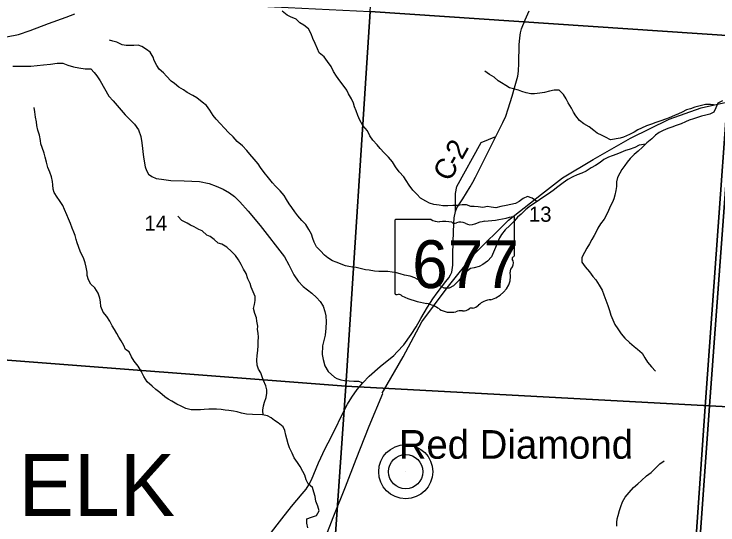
# Model space of a CAD drawing. Extents: x 0 to 34, y 0 to 22.
# Drawn here: x 3.275 to 5.215, y 15.589 to 16.998 of the extents above; entities that cross this region are included whole.
import ezdxf

# ---------------------------------------------------------------- set-up
doc = ezdxf.new("R2010")
doc.units = 0
for name, color, linetype in [('GM_X_County_Road', 7, 'Continuous'), ('GM_X_County_Road_Text', 7, 'Continuous'), ('GM_X_Minor_River', 7, 'Continuous'), ('GM_X_Rail_Line', 7, 'Continuous'), ('GM_X_Section', 7, 'Continuous'), ('GM_X_Section_Text', 7, 'Continuous'), ('GM_X_State_Location', 7, 'Continuous'), ('GM_X_State_Route', 7, 'Continuous'), ('GM_X_State_Shield', 7, 'Continuous'), ('GM_X_Township_Road', 7, 'Continuous'), ('GM_X_Township_Text', 7, 'Continuous'), ('GM_X_Unincorporated', 7, 'Continuous'), ('GM_X_Unincorporated_Location', 7, 'Continuous'), ('GM_X_Unincorporated_Text', 7, 'Continuous'), ('SC_Scratch1', 7, 'Continuous')]:
    doc.layers.add(name, color=color, linetype=linetype)

msp = doc.modelspace()

# ---------------------------------------------------------------- linework, layer by layer
at = {"layer": 'GM_X_County_Road'}
msp.add_lwpolyline([(4.4912, 16.4535), (4.4918, 16.5034), (4.4951, 16.5222), (4.5626, 16.6436), (4.6031, 16.6603)], dxfattribs=at)
at = {"layer": 'GM_X_Minor_River'}
for points in [[(4.7156, 16.481), (4.7031, 16.4897), (4.6902, 16.4946), (4.6781, 16.4889), (4.6668, 16.4809), (4.6565, 16.4759), (4.6441, 16.4725), (4.6312, 16.4698), (4.6165, 16.4671), (4.6028, 16.4633), (4.5896, 16.4655), (4.5794, 16.467), (4.5669, 16.4643), (4.5536, 16.4658), (4.5434, 16.4669), (4.5336, 16.4669), (4.5214, 16.4714), (4.5097, 16.4714), (4.498, 16.4702), (4.484, 16.4698), (4.4707, 16.4694), (4.4563, 16.469), (4.4461, 16.4705), (4.4321, 16.4731), (4.4203, 16.4765), (4.4093, 16.4822), (4.3953, 16.4897), (4.3851, 16.5014), (4.374, 16.5124), (4.3638, 16.526), (4.3554, 16.5393), (4.3493, 16.5491), (4.336, 16.5627), (4.3265, 16.5768), (4.3178, 16.5904), (4.3071, 16.6033), (4.2953, 16.6154), (4.2839, 16.6275), (4.2752, 16.6373), (4.2638, 16.6498), (4.2551, 16.6619), (4.2486, 16.6755), (4.2364, 16.6903), (4.228, 16.7054), (4.2223, 16.7179), (4.2177, 16.7308), (4.2135, 16.7418), (4.2101, 16.752), (4.2051, 16.7645), (4.1964, 16.7782), (4.1918, 16.7884), (4.1819, 16.802), (4.1728, 16.8134), (4.1633, 16.8262), (4.1553, 16.8395), (4.1488, 16.8535), (4.1389, 16.8668), (4.1294, 16.8796), (4.1162, 16.8906), (4.1112, 16.9016), (4.1047, 16.9171), (4.0982, 16.9304), (4.0933, 16.9432), (4.086, 16.9569), (4.0731, 16.9671), (4.0625, 16.9739), (4.0523, 16.9837), (4.0371, 16.9901), (4.0276, 16.995), (4.0136, 17.0056)], [(3.9046, 16.6345), (3.8902, 16.6462), (3.8784, 16.6595), (3.8663, 16.6712), (3.8545, 16.6833), (3.8431, 16.6965), (3.8317, 16.7083), (3.8237, 16.7181), (3.8146, 16.7332), (3.8051, 16.7457), (3.7937, 16.7552), (3.7789, 16.7669), (3.7679, 16.7737), (3.7523, 16.7816), (3.7421, 16.7888), (3.7292, 16.7964), (3.7174, 16.8066), (3.7076, 16.813), (3.6947, 16.8262), (3.6871, 16.8361), (3.6745, 16.8459), (3.6681, 16.8557), (3.6612, 16.8694), (3.6578, 16.8788), (3.6498, 16.8932), (3.6403, 16.9004), (3.6274, 16.908), (3.6168, 16.9117), (3.605, 16.9113), (3.5945, 16.9113), (3.5842, 16.9109), (3.5732, 16.9128), (3.5577, 16.9203), (3.5475, 16.9229), (3.538, 16.9256)], [(5.2121, 16.7463), (5.1943, 16.7488), (5.1803, 16.748), (5.1622, 16.7438), (5.1516, 16.7407), (5.1391, 16.7369), (5.1281, 16.7334), (5.116, 16.7273), (5.1058, 16.7228), (5.0952, 16.7182), (5.0805, 16.7121), (5.0703, 16.7083), (5.0574, 16.7037), (5.0435, 16.6987), (5.0317, 16.6941), (5.0177, 16.6892), (5.0041, 16.6835), (4.9939, 16.6785), (4.9837, 16.6724), (4.9713, 16.6659), (4.955, 16.6587), (4.9452, 16.656), (4.9187, 16.6514), (4.9054, 16.6586), (4.8956, 16.6627), (4.8823, 16.6695), (4.8724, 16.6767), (4.8595, 16.6865), (4.8451, 16.6948), (4.8337, 16.7043), (4.8235, 16.7171), (4.817, 16.7277), (4.8109, 16.738), (4.8021, 16.7535), (4.7964, 16.7637), (4.7888, 16.7758), (4.7774, 16.7879), (4.763, 16.7883), (4.7506, 16.7848), (4.7369, 16.7814), (4.7237, 16.7795), (4.7097, 16.7779), (4.6995, 16.7779), (4.6862, 16.7805), (4.6745, 16.7843), (4.665, 16.7877), (4.651, 16.7914), (4.6408, 16.7948), (4.6301, 16.8009), (4.6184, 16.808), (4.6089, 16.8141), (4.5979, 16.8235), (4.585, 16.8315), (4.5721, 16.8401)], [(5.2276, 16.7583), (5.2144, 16.7519), (5.2091, 16.7393), (5.2035, 16.7272), (5.1925, 16.7215), (5.1812, 16.7195), (5.1694, 16.7165), (5.1581, 16.7123), (5.1479, 16.7085), (5.1354, 16.705), (5.1256, 16.7008), (5.1131, 16.6955), (5.0999, 16.6905), (5.0874, 16.6856), (5.0764, 16.6821), (5.0636, 16.6764), (5.053, 16.6711), (5.0432, 16.6638), (5.0322, 16.6539), (5.019, 16.6425), (5.0066, 16.6308), (4.9949, 16.6197), (4.9843, 16.6106), (4.973, 16.5996), (4.9643, 16.5893), (4.9583, 16.5798), (4.9496, 16.5688), (4.9443, 16.5593), (4.9376, 16.5468), (4.9353, 16.535), (4.935, 16.5225), (4.9335, 16.5111), (4.9309, 16.4982), (4.9279, 16.4887), (4.9242, 16.4793), (4.9189, 16.4694), (4.9133, 16.4557), (4.9069, 16.4424), (4.9009, 16.4326), (4.8914, 16.4193), (4.8835, 16.4071), (4.879, 16.3969), (4.8737, 16.387), (4.867, 16.3763), (4.8606, 16.3646), (4.8538, 16.3524), (4.847, 16.3399), (4.8395, 16.3262), (4.8399, 16.3141), (4.849, 16.3008), (4.8608, 16.2868), (4.8699, 16.2743), (4.8787, 16.2645), (4.8874, 16.2505), (4.8954, 16.2365), (4.9004, 16.2232), (4.9057, 16.2085), (4.9118, 16.1944), (4.9161, 16.18), (4.9199, 16.1675), (4.9248, 16.155), (4.9306, 16.1418), (4.9386, 16.1297), (4.9481, 16.1164), (4.9579, 16.1043), (4.9712, 16.0922), (4.9838, 16.0812), (4.9932, 16.0737), (5.0058, 16.0623), (5.0134, 16.0502), (5.021, 16.0377), (5.0313, 16.0252), (5.0427, 16.0135)], [(3.4249, 16.4335), (3.4207, 16.4445), (3.4138, 16.4585), (3.4093, 16.4698), (3.4005, 16.4835), (3.3937, 16.4933), (3.3853, 16.5054), (3.3826, 16.5153), (3.3818, 16.527), (3.381, 16.5365), (3.3776, 16.549), (3.3734, 16.5623), (3.368, 16.5748), (3.3646, 16.5896), (3.3604, 16.6028), (3.3581, 16.6146), (3.352, 16.6301), (3.3489, 16.6396), (3.3474, 16.6494), (3.3447, 16.6638), (3.3404, 16.6779), (3.3378, 16.6904), (3.3366, 16.7002), (3.3339, 16.7131), (3.332, 16.7279), (3.33, 16.74)], [(5.0158, 16.6395), (4.9975, 16.6364), (4.9854, 16.6303), (4.9703, 16.6242), (4.96, 16.6212), (4.9472, 16.6162), (4.9359, 16.6112), (4.9234, 16.607), (4.9135, 16.6036), (4.9003, 16.5967), (4.8901, 16.5884), (4.8777, 16.5804), (4.8652, 16.5735), (4.852, 16.5648), (4.8395, 16.5594), (4.827, 16.5545), (4.8145, 16.5491), (4.8013, 16.5419), (4.7881, 16.5324), (4.7738, 16.5214), (4.7609, 16.5111), (4.7477, 16.5019), (4.7349, 16.4936), (4.7228, 16.486), (4.7107, 16.4776), (4.6978, 16.4692), (4.685, 16.4593), (4.6725, 16.4464), (4.6624, 16.4373), (4.6541, 16.4274), (4.6416, 16.4149), (4.628, 16.4027), (4.6186, 16.3901), (4.6129, 16.3807), (4.6069, 16.3681), (4.6021, 16.3541), (4.596, 16.3412), (4.5904, 16.3286), (4.5795, 16.3165), (4.5666, 16.307), (4.5564, 16.302), (4.5428, 16.2982), (4.533, 16.2963), (4.5201, 16.2864), (4.5096, 16.275), (4.4994, 16.2624), (4.4862, 16.2488), (4.4737, 16.2415), (4.4601, 16.2419), (4.4476, 16.2494), (4.4377, 16.2494), (4.4279, 16.2482), (4.415, 16.2516), (4.4055, 16.2546), (4.3926, 16.2629), (4.3794, 16.2709), (4.3669, 16.275), (4.3513, 16.2776), (4.3392, 16.2814), (4.3286, 16.284), (4.3172, 16.2863), (4.3051, 16.2878), (4.2911, 16.2877), (4.2805, 16.2881), (4.268, 16.2888), (4.2532, 16.2914), (4.2434, 16.2929), (4.2324, 16.2952), (4.2176, 16.2989), (4.2078, 16.3), (4.1976, 16.3015), (4.1881, 16.3034), (4.1623, 16.3139), (4.1528, 16.3177), (4.1399, 16.3256), (4.1305, 16.3328), (4.1191, 16.3446), (4.1084, 16.3559), (4.1016, 16.3684), (4.0985, 16.379), (4.0947, 16.3911), (4.0875, 16.404), (4.0787, 16.4173), (4.0684, 16.429), (4.0574, 16.4411), (4.0487, 16.4528), (4.0407, 16.4646), (4.0335, 16.4744), (4.0255, 16.4869), (4.0194, 16.4971), (4.0084, 16.51), (3.9955, 16.5229), (3.9871, 16.5327), (3.9765, 16.5463), (3.9643, 16.5607), (3.954, 16.5751), (3.9472, 16.5849), (3.9362, 16.5974), (3.9251, 16.6114), (3.9168, 16.6213), (3.9046, 16.6345)], [(4.0841, 15.5811), (4.0818, 15.5936), (4.0821, 15.6058), (4.095, 15.6107), (4.1086, 15.6153), (4.1161, 15.6282), (4.1123, 15.6411), (4.1069, 15.6544), (4.105, 15.6673), (4.1015, 15.6798), (4.0977, 15.6923), (4.0856, 15.7025), (4.0799, 15.7138), (4.0764, 15.726), (4.0707, 15.7366), (4.0638, 15.7498), (4.0562, 15.7612), (4.0471, 15.7741), (4.0414, 15.7869), (4.0338, 15.8017), (4.0299, 15.8123), (4.0265, 15.826), (4.0242, 15.8366), (4.0207, 15.8498), (4.0162, 15.8597), (4.0029, 15.8706), (3.9926, 15.8767), (3.9831, 15.8846), (3.9737, 15.8895), (3.9597, 15.8922), (3.9316, 15.8936), (3.9154, 15.8947), (3.9021, 15.8973), (3.8896, 15.9007), (3.8794, 15.903), (3.8669, 15.9048), (3.8563, 15.9059), (3.846, 15.9074), (3.8332, 15.9085), (3.8222, 15.9085), (3.8116, 15.9081), (3.7987, 15.9077), (3.7889, 15.9065), (3.776, 15.9061), (3.7631, 15.9061), (3.7484, 15.9102), (3.7355, 15.9162), (3.723, 15.9219), (3.7093, 15.9306), (3.6998, 15.9359), (3.69, 15.9427), (3.6767, 15.954), (3.6657, 15.9623), (3.6558, 15.9714), (3.6421, 15.9835), (3.6322, 15.9987), (3.6254, 16.0131), (3.617, 16.0267), (3.606, 16.0403), (3.5988, 16.0528), (3.5919, 16.0661), (3.582, 16.0732), (3.5778, 16.0842), (3.5698, 16.0971), (3.5638, 16.1069), (3.5584, 16.1172), (3.5516, 16.1278), (3.5455, 16.1384), (3.539, 16.1512), (3.5306, 16.1634), (3.5204, 16.1762), (3.5143, 16.1914), (3.5127, 16.2039), (3.5108, 16.2141), (3.5066, 16.2281), (3.4971, 16.2425), (3.4864, 16.2527), (3.4803, 16.2652), (3.4765, 16.2766), (3.4761, 16.2865), (3.4734, 16.3001), (3.4707, 16.3122), (3.4658, 16.3259), (3.4581, 16.3414), (3.4528, 16.3566), (3.4486, 16.3672), (3.4459, 16.3766), (3.4432, 16.3869), (3.4398, 16.3967), (3.4348, 16.4077), (3.4306, 16.4206), (3.4249, 16.4335)], [(3.9617, 15.8918), (3.9607, 15.9058), (3.9622, 15.9179), (3.9652, 15.9278), (3.9693, 15.94), (3.9716, 15.9525), (3.9719, 15.962), (3.9692, 15.9729), (3.9624, 15.987), (3.9589, 15.9972), (3.9547, 16.0089), (3.949, 16.0188), (3.9452, 16.0298), (3.9436, 16.043), (3.9447, 16.0559), (3.9466, 16.07), (3.9473, 16.0836), (3.9476, 16.0946), (3.9484, 16.1071), (3.9476, 16.1181), (3.946, 16.1276), (3.9467, 16.1375), (3.944, 16.1507), (3.9429, 16.1602), (3.9387, 16.1723), (3.9352, 16.186), (3.9371, 16.1966), (3.9389, 16.208), (3.9389, 16.2186), (3.9343, 16.2319), (3.9286, 16.2447), (3.9252, 16.2546), (3.9194, 16.2678), (3.9145, 16.2826), (3.9076, 16.2947), (3.9008, 16.3076), (3.8932, 16.3205), (3.8848, 16.3322), (3.8738, 16.3432), (3.8609, 16.3549), (3.8476, 16.3636), (3.8377, 16.3662), (3.826, 16.3764), (3.8153, 16.384), (3.8059, 16.3878), (3.7937, 16.4003), (3.7839, 16.4036), (3.771, 16.4108), (3.7611, 16.4153), (3.7516, 16.421), (3.7376, 16.4286), (3.7266, 16.4407)], [(4.9358, 15.5855), (4.9361, 15.5957), (4.9372, 15.6056), (4.9398, 15.6151), (4.9436, 15.6284), (4.9473, 15.6398), (4.9515, 15.6523), (4.959, 15.6652), (4.9699, 15.6789), (4.982, 15.6922), (4.9945, 15.7021), (5.0043, 15.7112), (5.0182, 15.7245), (5.0307, 15.7332), (5.0435, 15.7465), (5.0548, 15.7572), (5.0669, 15.7656)]]:
    msp.add_lwpolyline(points, dxfattribs=at)
at = {"layer": 'GM_X_Rail_Line'}
for points in [[(4.2898, 15.952), (4.3475, 16.0526), (4.3991, 16.1493), (4.4683, 16.2429), (4.543, 16.336), (4.6379, 16.4293), (4.7283, 16.5013), (4.7863, 16.5458), (4.871, 16.5969), (4.9741, 16.656), (5.0806, 16.7082), (5.1686, 16.7396), (5.2381, 16.7552)], [(4.098, 15.4643), (4.1545, 15.6095), (4.1881, 15.6942), (4.2177, 15.7701), (4.2538, 15.8616), (4.2913, 15.9518)]]:
    msp.add_lwpolyline(points, dxfattribs=at)
at = {"layer": 'GM_X_Section'}
for points in [[(4.3187, 18.0057), (5.3412, 17.9492), (5.2673, 16.9365), (4.2561, 17.0047)], [(3.2396, 17.0555), (4.2561, 17.0047), (4.189, 15.9719), (3.1721, 16.0496)], [(4.2561, 17.0047), (5.2673, 16.9365), (5.1915, 15.9177), (4.189, 15.9719)], [(6.2455, 16.872), (6.2183, 16.4683), (6.1917, 16.0616), (6.1792, 15.8658), (5.1915, 15.9177), (5.2673, 16.9365)], [(4.189, 15.9719), (4.1172, 14.9476), (3.1079, 15.0113), (3.1721, 16.0496)], [(5.1915, 15.9177), (5.117, 14.8733), (4.1172, 14.9476), (4.189, 15.9719)], [(5.1915, 15.9177), (6.1792, 15.8658), (6.168, 15.6897), (6.1161, 14.8127), (5.117, 14.8733)]]:
    msp.add_lwpolyline(points, close=True, dxfattribs=at)
at = {"layer": 'GM_X_State_Route'}
for points in [[(4.3963, 16.1586), (4.4144, 16.1898), (4.4292, 16.2126), (4.4408, 16.2293), (4.4652, 16.2602), (4.473, 16.2708), (4.4774, 16.2783), (4.481, 16.2858), (4.4826, 16.2926), (4.484, 16.3056), (4.4842, 16.333), (4.4855, 16.3709), (4.4865, 16.4199), (4.4876, 16.4355), (4.4912, 16.4535), (4.4954, 16.4633), (4.5114, 16.4883), (4.5319, 16.5212), (4.5391, 16.5342), (4.5464, 16.5481), (4.6031, 16.6603), (4.6103, 16.6746), (4.6221, 16.6986), (4.6299, 16.7164), (4.6367, 16.7368), (4.6475, 16.7718), (4.6545, 16.7948), (4.663, 16.8262), (4.6653, 16.8406), (4.6662, 16.8623), (4.6673, 16.9132), (4.6687, 16.9327), (4.6705, 16.9464), (4.6737, 16.9571), (4.6833, 16.982), (4.6942, 17.0068)], [(3.9777, 15.5609), (4.0133, 15.6056), (4.0393, 15.6395), (4.0687, 15.6746), (4.0799, 15.6879), (4.087, 15.6993), (4.0947, 15.7132), (4.1141, 15.76), (4.1321, 15.7994), (4.1485, 15.8313), (4.1886, 15.9121), (4.1941, 15.9221), (4.2055, 15.9414), (4.2203, 15.9625), (4.2364, 15.9807), (4.2532, 15.9989), (4.2835, 16.0256), (4.3211, 16.0566), (4.331, 16.0662), (4.349, 16.0858), (4.3695, 16.1146), (4.3827, 16.1351), (4.3963, 16.1586)]]:
    msp.add_lwpolyline(points, dxfattribs=at)
at = {"layer": 'GM_X_State_Shield'}
for p, q in [((4.4241, 16.4316), (4.3275, 16.4316)), ((4.6539, 16.3319), (4.6539, 16.4366)), ((4.3243, 16.4282), (4.3243, 16.2281)), ((4.6538, 16.3319), (4.6539, 16.3319))]:
    msp.add_line(p, q, dxfattribs=at)
for centre, major_axis, start_param, end_param in [((4.3281, 16.4286), (0.00382, 0), 1.712693, 3.28349), ((4.447, 16.4549), (0.037, 0), 4.042523, 4.731795), ((4.5365, 16.7045), (0.3495, 0), 4.814394, 5.042369), ((4.6502, 16.437), (0.00367, 0), 6.141152, 7.989035), ((4.4593, 16.3193), (0.133, 0), 1.404758, 1.657858), ((4.4895, 16.4297), (0.0107, 0), 3.836095, 5.185415), ((4.5052, 16.4065), (0.0222, 0), 0.950623, 2.079405), ((4.5339, 16.4383), (0.0267, 0), 4.081561, 5.145723), ((4.5811, 16.3705), (0.0703, 0), 1.699011, 2.107814), ((4.653, 16.3242), (0.00568, 0), 1.883978, 3.671073), ((4.6169, 16.311), (0.0341, 0), 5.934695, 6.695948), ((4.65, 16.3315), (0.00393, 0), 5.05454, 6.418171), ((4.667, 16.2881), (0.0248, 0), 2.387724, 3.262537), ((4.5561, 16.2748), (0.0874, 0), 5.101752, 6.440018), ((4.3281, 16.2276), (0.00385, 0), 3.00124, 4.508301), ((4.3287, 16.2481), (0.0294, 0), 4.665946, 4.897461), ((4.3347, 16.2165), (0.0106, 0), 0.519207, 1.627899), ((4.4685, 16.3963), (0.2524, 0), 4.195997, 4.488961), ((4.3933, 16.1382), (0.079, 0), 0.823519, 1.323587), ((4.5929, 16.1719), (0.0479, 0), 1.647645, 2.488434), ((4.4787, 16.2155), (0.0501, 0), 4.026481, 4.996735), ((4.5076, 16.1464), (0.0412, 0), 1.495662, 1.94098), ((4.5113, 16.2006), (0.0267, 0), 4.691044, 5.507374), ((4.5355, 16.1812), (0.00752, 0), 1.147584, 2.315152), ((4.5323, 16.2087), (0.0282, 0), 4.937069, 5.64225)]:
    msp.add_ellipse(centre, major_axis=major_axis, ratio=0.8, start_param=start_param, end_param=end_param, dxfattribs=at)
at = {"layer": 'GM_X_Township_Road'}
for points in [[(2.7265, 16.8799), (2.7344, 16.8819), (2.7581, 16.8864), (2.7935, 16.8897), (2.8339, 16.8933), (2.8651, 16.8954), (2.8913, 16.8972), (2.9105, 16.8969), (2.9358, 16.8962), (2.959, 16.8965), (2.983, 16.8976), (3.0005, 16.9004), (3.0382, 16.9054), (3.0564, 16.9081), (3.1157, 16.917), (3.1641, 16.9207), (3.2052, 16.9261), (3.2541, 16.9355), (3.2872, 16.9419), (3.3196, 16.9521), (3.3698, 16.9715), (3.4181, 16.9893), (3.4427, 16.9984)], [(3.2719, 16.8545), (3.2897, 16.8539), (3.3208, 16.8542), (3.3561, 16.8581), (3.3749, 16.86), (3.3937, 16.8623), (3.4092, 16.862), (3.4231, 16.8571), (3.4384, 16.8522), (3.4536, 16.8493), (3.4707, 16.8471), (3.4863, 16.8464), (3.496, 16.837), (3.5028, 16.8273), (3.5119, 16.814), (3.5358, 16.7716), (3.5481, 16.7583), (3.5808, 16.7201), (3.6064, 16.6942), (3.6178, 16.6783), (3.6239, 16.6602), (3.6272, 16.6427), (3.6317, 16.6035), (3.6359, 16.5766), (3.6395, 16.5663), (3.6453, 16.5559), (3.6544, 16.5498), (3.6664, 16.5446), (3.6815, 16.5421), (3.7065, 16.5387), (3.7434, 16.5381), (3.7862, 16.5362), (3.8127, 16.5303), (3.8322, 16.5232), (3.851, 16.5148), (3.8685, 16.5051), (3.8821, 16.495), (3.8969, 16.4804), (3.9203, 16.4545), (3.9527, 16.4144), (4.0203, 16.3282), (4.0317, 16.3062), (4.0459, 16.2787), (4.0582, 16.2612), (4.0718, 16.2463), (4.0955, 16.2283), (4.1088, 16.2165), (4.1188, 16.2052), (4.1266, 16.1919), (4.1314, 16.1773), (4.134, 16.1657), (4.1352, 16.1493), (4.134, 16.132), (4.1319, 16.1125), (4.1253, 16.0827), (4.1243, 16.0591), (4.1266, 16.0448), (4.1314, 16.0277), (4.1408, 16.0118), (4.1576, 15.9963), (4.1648, 15.9927), (4.1758, 15.9893), (4.1853, 15.9869), (4.1983, 15.9862), (4.2113, 15.9857), (4.224, 15.9851), (4.2364, 15.9807)]]:
    msp.add_lwpolyline(points, dxfattribs=at)
at = {"layer": 'GM_X_Unincorporated'}
for radius in [0.0744, 0.0472]:
    msp.add_circle((4.3543, 15.7357), radius, dxfattribs=at)
at = {"layer": 'GM_X_Unincorporated_Location'}
msp.add_line((4.3543, 15.7357), (4.3543, 15.7357), dxfattribs=at)
at = {"layer": 'SC_Scratch1'}
for points in [[(2.1, 19.1982), (2.1, 14.1), (5.0535, 14.1), (5.0814, 14.5016), (5.1049, 14.8414), (5.1794, 15.9156), (5.2761, 17.2534), (5.2869, 17.4026), (5.3506, 18.2846), (5.3662, 18.4999), (5.4007, 18.9779), (5.182, 18.9932), (4.7997, 19.0196), (4.7394, 19.0241), (4.3628, 19.0495), (3.3448, 19.1146), (2.3572, 19.1804)], [(5.0535, 14.1), (8.9, 14.1), (8.9, 18.7389), (8.2061, 18.7863), (7.2159, 18.8539), (6.8273, 18.8804), (5.9889, 18.9377), (5.4885, 18.9719), (5.4007, 18.9779), (5.3662, 18.4999), (5.3506, 18.2846), (5.2869, 17.4026), (5.2761, 17.2534), (5.1794, 15.9156), (5.1049, 14.8414), (5.0814, 14.5016)]]:
    msp.add_lwpolyline(points, close=True, dxfattribs=at)

# ---------------------------------------------------------------- texts
at = {"layer": 'GM_X_County_Road_Text'}
for s, rotation, p in [('2', 60.6644, (4.5094, 16.5936)), ('C', 60.9088, (4.4757, 16.533)), ('-', 60.9088, (4.4982, 16.5735))]:
    msp.add_text(s, height=0.0568, rotation=rotation, dxfattribs=at).set_placement(p)
at = {"layer": 'GM_X_Section_Text'}
for s, p in [('13', (4.6939, 16.425)), ('14', (3.6344, 16.4003))]:
    msp.add_text(s, height=0.04186, rotation=0, dxfattribs=at).set_placement(p)
at = {"layer": 'GM_X_State_Location'}
for s in ['s', 'r']:
    msp.add_text(s, height=0.000189, dxfattribs=at).set_placement((4.4854, 16.3148))
msp.add_text('677', height=0.000189, rotation=0, dxfattribs=at).set_placement((4.4185, 16.3011))
at = {"layer": 'GM_X_State_Shield'}
msp.add_text('677', height=0.13184, dxfattribs=at).set_placement((4.3721, 16.2422))
at = {"layer": 'GM_X_Township_Text'}
msp.add_text('ELK', height=0.17045, rotation=0, dxfattribs=at).set_placement((3.2873, 15.6141))
at = {"layer": 'GM_X_Unincorporated_Text'}
msp.add_text('Red Diamond', height=0.078977, rotation=0, dxfattribs=at).set_placement((4.3352, 15.7716))

doc.saveas('drawing.dxf')
